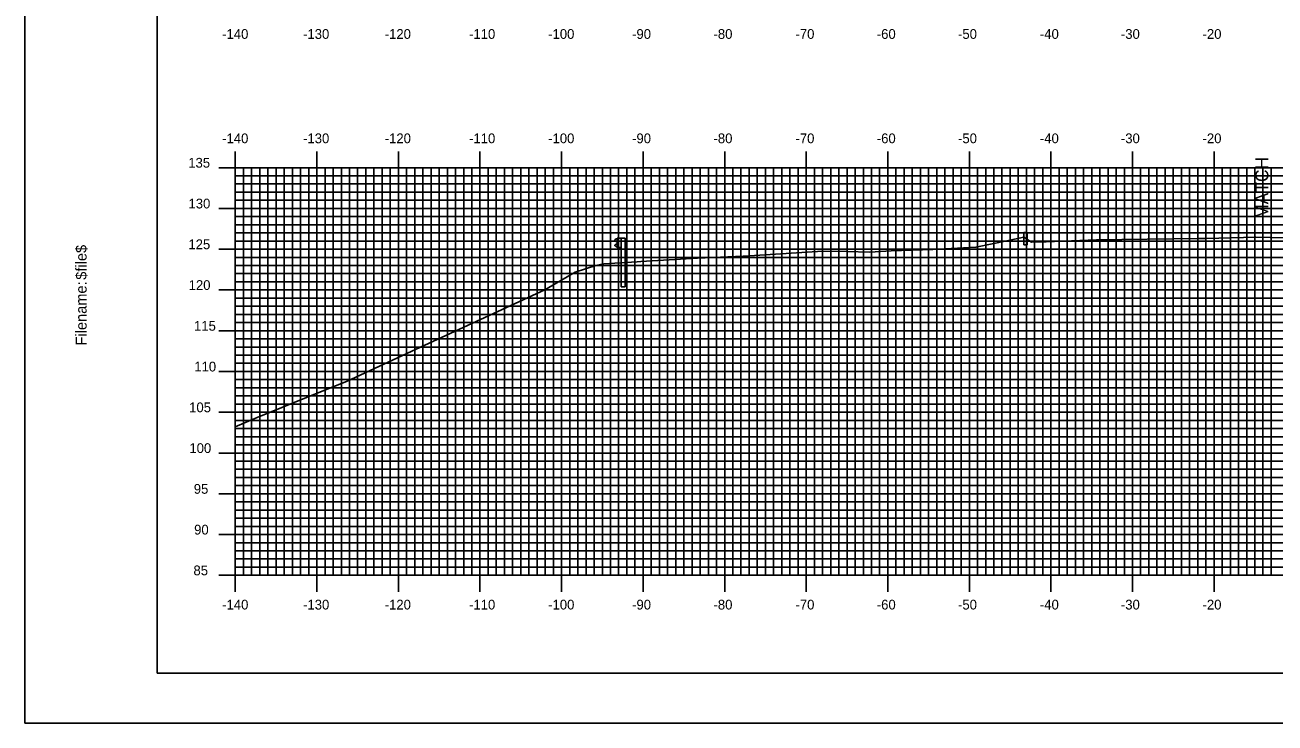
# Model space of a CAD drawing. Extents: x 858052 to 858395, y 364366 to 364586.
# Drawn here: x 858051.6 to 858204.8, y 364365.7 to 364451.3 of the extents above; entities that cross this region are included whole.
import ezdxf

# ---------------------------------------------------------------- set-up
doc = ezdxf.new("R2010")
doc.units = 0
for name, color, linetype in [('ANNOTATION', 7, 'Continuous'), ('BORDER', 7, 'Continuous'), ('H_V ANNOTATION', 7, 'Continuous'), ('M_Guardrail', 7, 'Continuous'), ('M_Roadway_Centerline', 7, 'Continuous'), ('MAJOR', 7, 'Continuous'), ('MINOR', 7, 'Continuous'), ('PLOT BOUNDARY', 7, 'Continuous'), ('S_Curb_Type_1', 7, 'Continuous'), ('S_Roadway_Centerline', 7, 'Continuous')]:
    doc.layers.add(name, color=color, linetype=linetype)

msp = doc.modelspace()

# ---------------------------------------------------------------- linework, layer by layer
at = {"layer": 'BORDER'}
msp.add_lwpolyline([(858067.76, 364371.79), (858387.76, 364371.79), (858387.76, 364581.79), (858067.76, 364581.79)], close=True, dxfattribs=at)
at = {"layer": 'M_Guardrail'}
for p, q in [((858124.07, 364425.06), (858123.93, 364424.96)), ((858123.93, 364424.82), (858124.12, 364424.68)), ((858124.12, 364424.46), (858123.93, 364424.33)), ((858123.93, 364424.19), (858124.07, 364424.09)), ((858124.17, 364425.08), (858124.09, 364425.07)), ((858124.09, 364424.08), (858124.17, 364424.06)), ((858124.16, 364424.62), (858124.16, 364424.53)), ((858124.17, 364425.16), (858124.66, 364425.16)), ((858124.17, 364423.99), (858124.17, 364425.16)), ((858124.66, 364423.99), (858124.17, 364423.99)), ((858124.66, 364425.16), (858125.15, 364425.16)), ((858124.66, 364425.16), (858124.66, 364423.99)), ((858124.66, 364419.16), (858124.66, 364423.99)), ((858125.15, 364425.16), (858125.15, 364419.16)), ((858124.66, 364419.16), (858125.15, 364419.16))]:
    msp.add_line(p, q, dxfattribs=at)
for centre, major_axis, start_param, end_param in [((858123.98, 364424.89), (-0.0877, 0), 5.323254, 7.243116), ((858123.98, 364424.26), (-0.0877, 0), 5.323254, 7.243116), ((858124.1, 364425.03), (-0.0417, 0), 4.886922, 5.323254), ((858124.1, 364424.12), (-0.0417, 0), 0.959931, 1.396263), ((858124.08, 364424.62), (0.0789, 0), 0, 0.959931), ((858124.08, 364424.53), (0.0789, 0), 5.323254, 6.283185)]:
    msp.add_ellipse(centre, major_axis=major_axis, ratio=0.995501, start_param=start_param, end_param=end_param, dxfattribs=at)
at = {"layer": 'MAJOR'}
for p, q in [((858077.36, 364435.79), (858077.36, 364433.79)), ((858087.36, 364435.79), (858087.36, 364433.79)), ((858097.36, 364435.79), (858097.36, 364433.79)), ((858107.36, 364435.79), (858107.36, 364433.79)), ((858117.36, 364435.79), (858117.36, 364433.79)), ((858127.36, 364435.79), (858127.36, 364433.79)), ((858137.36, 364435.79), (858137.36, 364433.79)), ((858147.36, 364435.79), (858147.36, 364433.79)), ((858157.36, 364435.79), (858157.36, 364433.79)), ((858167.36, 364435.79), (858167.36, 364433.79)), ((858177.36, 364435.79), (858177.36, 364433.79)), ((858187.36, 364435.79), (858187.36, 364433.79)), ((858197.36, 364435.79), (858197.36, 364433.79)), ((858075.36, 364433.79), (858077.36, 364433.79)), ((858077.36, 364433.79), (858357.36, 364433.79)), ((858077.36, 364383.79), (858077.36, 364433.79)), ((858077.36, 364383.79), (858077.36, 364433.79)), ((858077.36, 364433.79), (858357.36, 364433.79)), ((858087.36, 364383.79), (858087.36, 364433.79)), ((858097.36, 364383.79), (858097.36, 364433.79)), ((858107.36, 364383.79), (858107.36, 364433.79)), ((858117.36, 364383.79), (858117.36, 364433.79)), ((858127.36, 364383.79), (858127.36, 364433.79)), ((858137.36, 364383.79), (858137.36, 364433.79)), ((858147.36, 364383.79), (858147.36, 364433.79)), ((858157.36, 364383.79), (858157.36, 364433.79)), ((858167.36, 364383.79), (858167.36, 364433.79)), ((858177.36, 364383.79), (858177.36, 364433.79)), ((858187.36, 364383.79), (858187.36, 364433.79)), ((858197.36, 364383.79), (858197.36, 364433.79)), ((858075.36, 364428.79), (858077.36, 364428.79)), ((858077.36, 364428.79), (858357.36, 364428.79)), ((858075.36, 364423.79), (858077.36, 364423.79)), ((858077.36, 364423.79), (858357.36, 364423.79)), ((858075.36, 364418.79), (858077.36, 364418.79)), ((858077.36, 364418.79), (858357.36, 364418.79)), ((858075.36, 364413.79), (858077.36, 364413.79)), ((858077.36, 364413.79), (858357.36, 364413.79)), ((858075.36, 364408.79), (858077.36, 364408.79)), ((858077.36, 364408.79), (858357.36, 364408.79)), ((858075.36, 364403.79), (858077.36, 364403.79)), ((858077.36, 364403.79), (858357.36, 364403.79)), ((858075.36, 364398.79), (858077.36, 364398.79)), ((858077.36, 364398.79), (858357.36, 364398.79)), ((858075.36, 364393.79), (858077.36, 364393.79)), ((858077.36, 364393.79), (858357.36, 364393.79)), ((858075.36, 364388.79), (858077.36, 364388.79)), ((858077.36, 364388.79), (858357.36, 364388.79)), ((858075.36, 364383.79), (858077.36, 364383.79)), ((858077.36, 364383.79), (858357.36, 364383.79)), ((858077.36, 364383.79), (858357.36, 364383.79)), ((858077.36, 364381.78), (858077.36, 364383.79)), ((858087.36, 364381.78), (858087.36, 364383.79)), ((858097.36, 364381.78), (858097.36, 364383.79)), ((858107.36, 364381.78), (858107.36, 364383.79)), ((858117.36, 364381.78), (858117.36, 364383.79)), ((858127.36, 364381.78), (858127.36, 364383.79)), ((858137.36, 364381.78), (858137.36, 364383.79)), ((858147.36, 364381.78), (858147.36, 364383.79)), ((858157.36, 364381.78), (858157.36, 364383.79)), ((858167.36, 364381.78), (858167.36, 364383.79)), ((858177.36, 364381.78), (858177.36, 364383.79)), ((858187.36, 364381.78), (858187.36, 364383.79)), ((858197.36, 364381.78), (858197.36, 364383.79))]:
    msp.add_line(p, q, dxfattribs=at)
at = {"layer": 'MINOR'}
for p, q in [((858078.36, 364383.79), (858078.36, 364433.79)), ((858079.36, 364383.79), (858079.36, 364433.79)), ((858080.36, 364383.79), (858080.36, 364433.79)), ((858081.36, 364383.79), (858081.36, 364433.79)), ((858082.36, 364383.79), (858082.36, 364433.79)), ((858083.36, 364383.79), (858083.36, 364433.79)), ((858084.36, 364383.79), (858084.36, 364433.79)), ((858085.36, 364383.79), (858085.36, 364433.79)), ((858086.36, 364383.79), (858086.36, 364433.79)), ((858088.36, 364383.79), (858088.36, 364433.79)), ((858089.36, 364383.79), (858089.36, 364433.79)), ((858090.36, 364383.79), (858090.36, 364433.79)), ((858091.36, 364383.79), (858091.36, 364433.79)), ((858092.36, 364383.79), (858092.36, 364433.79)), ((858093.36, 364383.79), (858093.36, 364433.79)), ((858094.36, 364383.79), (858094.36, 364433.79)), ((858095.36, 364383.79), (858095.36, 364433.79)), ((858096.36, 364383.79), (858096.36, 364433.79)), ((858098.36, 364383.79), (858098.36, 364433.79)), ((858099.36, 364383.79), (858099.36, 364433.79)), ((858100.36, 364383.79), (858100.36, 364433.79)), ((858101.36, 364383.79), (858101.36, 364433.79)), ((858102.36, 364383.79), (858102.36, 364433.79)), ((858103.36, 364383.79), (858103.36, 364433.79)), ((858104.36, 364383.79), (858104.36, 364433.79)), ((858105.36, 364383.79), (858105.36, 364433.79)), ((858106.36, 364383.79), (858106.36, 364433.79)), ((858108.36, 364383.79), (858108.36, 364433.79)), ((858109.36, 364383.79), (858109.36, 364433.79)), ((858110.36, 364383.79), (858110.36, 364433.79)), ((858111.36, 364383.79), (858111.36, 364433.79)), ((858112.36, 364383.79), (858112.36, 364433.79)), ((858113.36, 364383.79), (858113.36, 364433.79)), ((858114.36, 364383.79), (858114.36, 364433.79)), ((858115.36, 364383.79), (858115.36, 364433.79)), ((858116.36, 364383.79), (858116.36, 364433.79)), ((858118.36, 364383.79), (858118.36, 364433.79)), ((858119.36, 364383.79), (858119.36, 364433.79)), ((858120.36, 364383.79), (858120.36, 364433.79)), ((858121.36, 364383.79), (858121.36, 364433.79)), ((858122.36, 364383.79), (858122.36, 364433.79)), ((858123.36, 364383.79), (858123.36, 364433.79)), ((858124.36, 364383.79), (858124.36, 364433.79)), ((858125.36, 364383.79), (858125.36, 364433.79)), ((858126.36, 364383.79), (858126.36, 364433.79)), ((858128.36, 364383.79), (858128.36, 364433.79)), ((858129.36, 364383.79), (858129.36, 364433.79)), ((858130.36, 364383.79), (858130.36, 364433.79)), ((858131.36, 364383.79), (858131.36, 364433.79)), ((858132.36, 364383.79), (858132.36, 364433.79)), ((858133.36, 364383.79), (858133.36, 364433.79)), ((858134.36, 364383.79), (858134.36, 364433.79)), ((858135.36, 364383.79), (858135.36, 364433.79)), ((858136.36, 364383.79), (858136.36, 364433.79)), ((858138.36, 364383.79), (858138.36, 364433.79)), ((858139.36, 364383.79), (858139.36, 364433.79)), ((858140.36, 364383.79), (858140.36, 364433.79)), ((858141.36, 364383.79), (858141.36, 364433.79)), ((858142.36, 364383.79), (858142.36, 364433.79)), ((858143.36, 364383.79), (858143.36, 364433.79)), ((858144.36, 364383.79), (858144.36, 364433.79)), ((858145.36, 364383.79), (858145.36, 364433.79)), ((858146.36, 364383.79), (858146.36, 364433.79)), ((858148.36, 364383.79), (858148.36, 364433.79)), ((858149.36, 364383.79), (858149.36, 364433.79)), ((858150.36, 364383.79), (858150.36, 364433.79)), ((858151.36, 364383.79), (858151.36, 364433.79)), ((858152.36, 364383.79), (858152.36, 364433.79)), ((858153.36, 364383.79), (858153.36, 364433.79)), ((858154.36, 364383.79), (858154.36, 364433.79)), ((858155.36, 364383.79), (858155.36, 364433.79)), ((858156.36, 364383.79), (858156.36, 364433.79)), ((858158.36, 364383.79), (858158.36, 364433.79)), ((858159.36, 364383.79), (858159.36, 364433.79)), ((858160.36, 364383.79), (858160.36, 364433.79)), ((858161.36, 364383.79), (858161.36, 364433.79)), ((858162.36, 364383.79), (858162.36, 364433.79)), ((858163.36, 364383.79), (858163.36, 364433.79)), ((858164.36, 364383.79), (858164.36, 364433.79)), ((858165.36, 364383.79), (858165.36, 364433.79)), ((858166.36, 364383.79), (858166.36, 364433.79)), ((858168.36, 364383.79), (858168.36, 364433.79)), ((858169.36, 364383.79), (858169.36, 364433.79)), ((858170.36, 364383.79), (858170.36, 364433.79)), ((858171.36, 364383.79), (858171.36, 364433.79)), ((858172.36, 364383.79), (858172.36, 364433.79)), ((858173.36, 364383.79), (858173.36, 364433.79)), ((858174.36, 364383.79), (858174.36, 364433.79)), ((858175.36, 364383.79), (858175.36, 364433.79)), ((858176.36, 364383.79), (858176.36, 364433.79)), ((858178.36, 364383.79), (858178.36, 364433.79)), ((858179.36, 364383.79), (858179.36, 364433.79)), ((858180.36, 364383.79), (858180.36, 364433.79)), ((858181.36, 364383.79), (858181.36, 364433.79)), ((858182.36, 364383.79), (858182.36, 364433.79)), ((858183.36, 364383.79), (858183.36, 364433.79)), ((858184.36, 364383.79), (858184.36, 364433.79)), ((858185.36, 364383.79), (858185.36, 364433.79)), ((858186.36, 364383.79), (858186.36, 364433.79)), ((858188.36, 364383.79), (858188.36, 364433.79)), ((858189.36, 364383.79), (858189.36, 364433.79)), ((858190.36, 364383.79), (858190.36, 364433.79)), ((858191.36, 364383.79), (858191.36, 364433.79)), ((858192.36, 364383.79), (858192.36, 364433.79)), ((858193.36, 364383.79), (858193.36, 364433.79)), ((858194.36, 364383.79), (858194.36, 364433.79)), ((858195.36, 364383.79), (858195.36, 364433.79)), ((858196.36, 364383.79), (858196.36, 364433.79)), ((858198.36, 364383.79), (858198.36, 364433.79)), ((858199.36, 364383.79), (858199.36, 364433.79)), ((858200.36, 364383.79), (858200.36, 364433.79)), ((858201.36, 364383.79), (858201.36, 364433.79)), ((858202.36, 364383.79), (858202.36, 364433.79)), ((858203.36, 364383.79), (858203.36, 364433.79)), ((858204.36, 364383.79), (858204.36, 364433.79)), ((858077.36, 364432.79), (858357.36, 364432.79)), ((858077.36, 364432.79), (858079.37, 364432.79)), ((858077.36, 364431.79), (858357.36, 364431.79)), ((858077.36, 364431.79), (858079.37, 364431.79)), ((858077.36, 364430.79), (858357.36, 364430.79)), ((858077.36, 364430.79), (858079.37, 364430.79)), ((858077.36, 364429.79), (858357.36, 364429.79)), ((858077.36, 364429.79), (858079.37, 364429.79)), ((858077.36, 364427.79), (858357.36, 364427.79)), ((858077.36, 364427.79), (858079.37, 364427.79)), ((858077.36, 364426.79), (858357.36, 364426.79)), ((858077.36, 364426.79), (858079.37, 364426.79)), ((858077.36, 364425.79), (858357.36, 364425.79)), ((858077.36, 364425.79), (858079.37, 364425.79)), ((858077.36, 364424.79), (858357.36, 364424.79)), ((858077.36, 364424.79), (858079.37, 364424.79)), ((858077.36, 364422.79), (858357.36, 364422.79)), ((858077.36, 364422.79), (858079.37, 364422.79)), ((858077.36, 364421.79), (858357.36, 364421.79)), ((858077.36, 364421.79), (858079.37, 364421.79)), ((858077.36, 364420.79), (858357.36, 364420.79)), ((858077.36, 364420.79), (858079.37, 364420.79)), ((858077.36, 364419.79), (858357.36, 364419.79)), ((858077.36, 364419.79), (858079.37, 364419.79)), ((858077.36, 364417.79), (858357.36, 364417.79)), ((858077.36, 364417.79), (858079.37, 364417.79)), ((858077.36, 364416.79), (858357.36, 364416.79)), ((858077.36, 364416.79), (858079.37, 364416.79)), ((858077.36, 364415.79), (858357.36, 364415.79)), ((858077.36, 364415.79), (858079.37, 364415.79)), ((858077.36, 364414.79), (858357.36, 364414.79)), ((858077.36, 364414.79), (858079.37, 364414.79)), ((858077.36, 364412.79), (858357.36, 364412.79)), ((858077.36, 364412.79), (858079.37, 364412.79)), ((858077.36, 364411.79), (858357.36, 364411.79)), ((858077.36, 364411.79), (858079.37, 364411.79)), ((858077.36, 364410.79), (858357.36, 364410.79)), ((858077.36, 364410.79), (858079.37, 364410.79)), ((858077.36, 364409.79), (858357.36, 364409.79)), ((858077.36, 364409.79), (858079.37, 364409.79)), ((858077.36, 364407.79), (858357.36, 364407.79)), ((858077.36, 364407.79), (858079.37, 364407.79)), ((858077.36, 364406.79), (858357.36, 364406.79)), ((858077.36, 364406.79), (858079.37, 364406.79)), ((858077.36, 364405.79), (858357.36, 364405.79)), ((858077.36, 364405.79), (858079.37, 364405.79)), ((858077.36, 364404.79), (858357.36, 364404.79)), ((858077.36, 364404.79), (858079.37, 364404.79)), ((858077.36, 364402.79), (858357.36, 364402.79)), ((858077.36, 364402.79), (858079.37, 364402.79)), ((858077.36, 364401.79), (858357.36, 364401.79)), ((858077.36, 364401.79), (858079.37, 364401.79)), ((858077.36, 364400.79), (858357.36, 364400.79)), ((858077.36, 364400.79), (858079.37, 364400.79)), ((858077.36, 364399.79), (858357.36, 364399.79)), ((858077.36, 364399.79), (858079.37, 364399.79)), ((858077.36, 364397.79), (858357.36, 364397.79)), ((858077.36, 364397.79), (858079.37, 364397.79)), ((858077.36, 364396.79), (858357.36, 364396.79)), ((858077.36, 364396.79), (858079.37, 364396.79)), ((858077.36, 364395.79), (858357.36, 364395.79)), ((858077.36, 364395.79), (858079.37, 364395.79)), ((858077.36, 364394.79), (858357.36, 364394.79)), ((858077.36, 364394.79), (858079.37, 364394.79)), ((858077.36, 364392.79), (858357.36, 364392.79)), ((858077.36, 364392.79), (858079.37, 364392.79)), ((858077.36, 364391.79), (858357.36, 364391.79)), ((858077.36, 364391.79), (858079.37, 364391.79)), ((858077.36, 364390.79), (858357.36, 364390.79)), ((858077.36, 364390.79), (858079.37, 364390.79)), ((858077.36, 364389.79), (858357.36, 364389.79)), ((858077.36, 364389.79), (858079.37, 364389.79)), ((858077.36, 364387.79), (858357.36, 364387.79)), ((858077.36, 364387.79), (858079.37, 364387.79)), ((858077.36, 364386.79), (858357.36, 364386.79)), ((858077.36, 364386.79), (858079.37, 364386.79)), ((858077.36, 364385.79), (858357.36, 364385.79)), ((858077.36, 364385.79), (858079.37, 364385.79)), ((858077.36, 364384.79), (858357.36, 364384.79)), ((858077.36, 364384.79), (858079.37, 364384.79))]:
    msp.add_line(p, q, dxfattribs=at)
at = {"layer": 'PLOT BOUNDARY'}
msp.add_lwpolyline([(858051.57, 364365.67), (858391.57, 364365.67), (858391.57, 364585.67), (858051.57, 364585.67)], close=True, dxfattribs=at)
at = {"layer": 'S_Curb_Type_1'}
msp.add_lwpolyline([(858174.04, 364425.83), (858174.46, 364425.83), (858174.46, 364424.33), (858174.04, 364424.33)], close=True, dxfattribs=at)
msp.add_lwpolyline([(858174.04, 364425.83), (858174.46, 364425.83), (858174.46, 364424.33), (858174.04, 364424.33)], close=True, dxfattribs=at)
at = {"layer": 'S_Roadway_Centerline'}
msp.add_lwpolyline([(858077.36, 364402.01), (858080.04, 364403.14), (858087.59, 364406.23), (858090.99, 364407.57), (858099.52, 364411.53), (858115.32, 364418.82), (858119.02, 364420.98), (858121.58, 364421.79), (858122.55, 364422.01), (858126.61, 364422.24), (858127.1, 364422.27), (858134.02, 364422.68), (858139.63, 364422.92), (858141.03, 364423.01), (858149.38, 364423.53), (858152.32, 364423.51), (858155.15, 364423.43), (858157.77, 364423.6), (858162.88, 364423.74), (858168.17, 364424.02), (858172.16, 364424.87), (858172.32, 364424.88), (858174.04, 364425.25), (858174.05, 364425.25), (858174.97, 364424.65), (858176.76, 364424.69), (858182.96, 364424.94), (858195.36, 364425.09), (858195.96, 364425.09), (858196.43, 364425.11), (858202.5, 364425.27), (858204.22, 364425.23), (858208.4, 364425.14)], dxfattribs=at)

# ---------------------------------------------------------------- texts
at = {"layer": 'ANNOTATION'}
msp.add_text('MATCH', height=1.6, rotation=90, dxfattribs=at).set_placement((858204.02, 364427.51))
at = {"layer": 'BORDER'}
for s, p in [('$file$', (858059.13, 364420.04)), ('Filename:', (858059.13, 364411.98))]:
    msp.add_text(s, height=1.339, rotation=90, dxfattribs=at).set_placement(p)
at = {"layer": 'H_V ANNOTATION'}
for s, p in [('-140', (858075.75, 364449.59)), ('-130', (858085.67, 364449.59)), ('-120', (858095.68, 364449.59)), ('-110', (858106.02, 364449.59)), ('-100', (858115.72, 364449.59)), ('-90', (858126.01, 364449.59)), ('-80', (858135.99, 364449.59)), ('-70', (858146.04, 364449.59)), ('-60', (858156.01, 364449.59)), ('-50', (858165.97, 364449.59)), ('-40', (858176.01, 364449.59)), ('-30', (858185.94, 364449.59)), ('-20', (858195.95, 364449.59)), ('-140', (858075.75, 364436.79)), ('-130', (858085.67, 364436.79)), ('-120', (858095.68, 364436.79)), ('-110', (858106.02, 364436.79)), ('-100', (858115.72, 364436.79)), ('-90', (858126.01, 364436.79)), ('-80', (858135.99, 364436.79)), ('-70', (858146.04, 364436.79)), ('-60', (858156.01, 364436.79)), ('-50', (858165.97, 364436.79)), ('-40', (858176.01, 364436.79)), ('-30', (858185.94, 364436.79)), ('-20', (858195.95, 364436.79)), ('135', (858071.59, 364433.79)), ('130', (858071.62, 364428.79)), ('125', (858071.61, 364423.79)), ('120', (858071.64, 364418.79)), ('115', (858072.3, 364413.79)), ('110', (858072.33, 364408.79)), ('105', (858071.7, 364403.79)), ('100', (858071.73, 364398.79)), ('95', (858072.27, 364393.79)), ('90', (858072.31, 364388.79)), ('85', (858072.23, 364383.79)), ('-140', (858075.75, 364379.59)), ('-130', (858085.67, 364379.59)), ('-120', (858095.68, 364379.59)), ('-110', (858106.02, 364379.59)), ('-100', (858115.72, 364379.59)), ('-90', (858126.01, 364379.59)), ('-80', (858135.99, 364379.59)), ('-70', (858146.04, 364379.59)), ('-60', (858156.01, 364379.59)), ('-50', (858165.97, 364379.59)), ('-40', (858176.01, 364379.59)), ('-30', (858185.94, 364379.59)), ('-20', (858195.95, 364379.59))]:
    msp.add_text(s, height=1.2, dxfattribs=at).set_placement(p)
at = {"layer": 'M_Roadway_Centerline'}
for s, p in [('C', (858202.5, 364425.27)), ('L', (858202.5, 364425.27)), ('C', (858141.02, 364423.01)), ('L', (858141.03, 364423))]:
    msp.add_text(s, height=0.0146, dxfattribs=at).set_placement(p)
at = {"layer": 'MAJOR'}
msp.add_text('-', height=0.012, dxfattribs=at).set_placement((858077.35, 364383.79))

doc.saveas('drawing.dxf')
